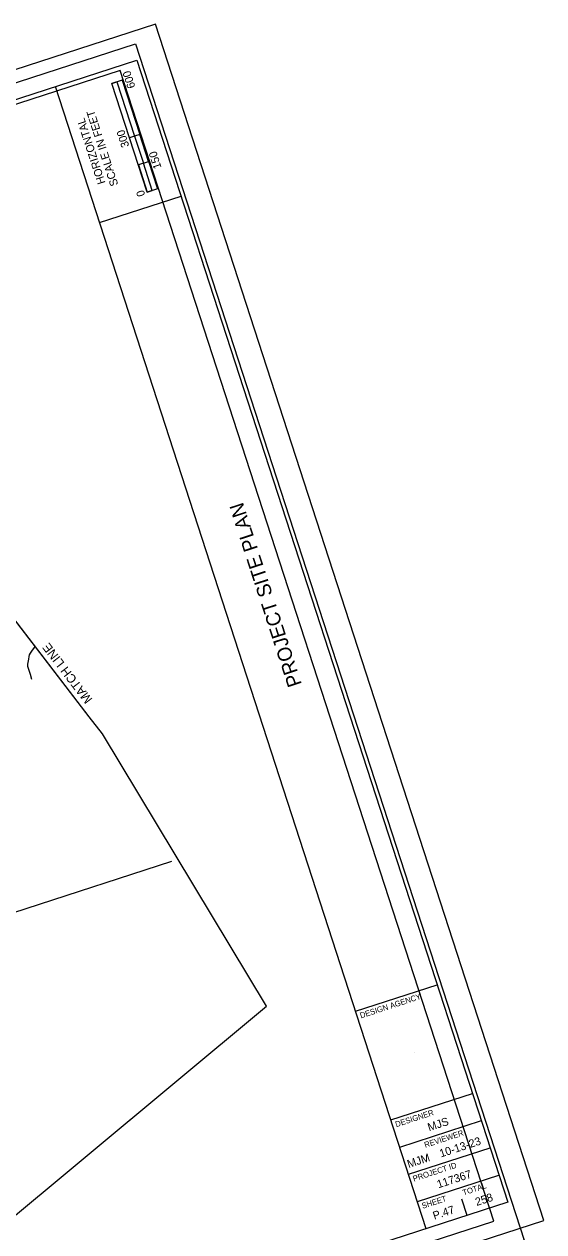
# Model space of a CAD drawing. Extents: x -468541894 to 3393103, y -306086142 to 1227927.
# Drawn here: x 1848366 to 1851093, y 537942 to 544279 of the extents above; entities that cross this region are included whole.
import ezdxf

# ---------------------------------------------------------------- set-up
doc = ezdxf.new("R2010")
doc.units = 0
for name, color, linetype in [('DT_X_Contour_Minor', 7, 'Continuous'), ('DT_X_Terrain_Ground_Line', 7, 'Continuous'), ('Level 14', 7, 'Continuous'), ('Level 63', 7, 'Continuous'), ('SC_Scratch1', 7, 'Continuous'), ('SH_Border', 7, 'Continuous'), ('SH_Cut_Line', 7, 'Continuous'), ('SH_Data', 7, 'Continuous')]:
    doc.layers.add(name, color=color, linetype=linetype)

msp = doc.modelspace()

# ---------------------------------------------------------------- linework, layer by layer
at = {"layer": 'DT_X_Contour_Minor'}
msp.add_lwpolyline([(1848407.5, 540841.3), (1848399.1, 540867.5), (1848386.1, 540908.3), (1848385.3, 540914.1), (1848386, 540921.4), (1848390.3, 540947.8), (1848392.7, 540960.7), (1848394.9, 540969.8), (1848399, 540978.1), (1848407.2, 540989.7), (1848420.5, 541008), (1848423.8, 541013.8)], dxfattribs=at)
at = {"layer": 'DT_X_Terrain_Ground_Line'}
msp.add_line((1848707.4, 540644.4), (1847509.3, 542205.2), dxfattribs=at)
at = {"layer": 'Level 14'}
msp.add_lwpolyline([(1845828.7, 538810.8), (1845878, 538827), (1845930.3, 538844), (1845983.1, 538861.1), (1846032.1, 538877.7), (1846083.4, 538894.3), (1849141.5, 539887)], dxfattribs=at)
at = {"layer": 'Level 63'}
for points in [[(1839250.2, 541026.2), (1848951, 544175.6), (1850988.8, 537898.9), (1841288, 534749.5)], [(1841356.9, 534923.2), (1850830.2, 537998.8), (1848870, 544036.6), (1839396.7, 540961)]]:
    msp.add_lwpolyline(points, close=True, dxfattribs=at)
at = {"layer": 'SC_Scratch1'}
msp.add_lwpolyline([(1841571, 538709.7), (1842189.3, 536805.3), (1843431.2, 536688.2), (1846191.5, 536987.1), (1848203, 537933.4), (1849637.7, 539126.1), (1848778.3, 540555.8), (1848707.4, 540644.4), (1847509.3, 542205.2), (1846552.9, 542298.5), (1845079.9, 541287.2), (1841825, 539212.4)], close=True, dxfattribs=at)
at = {"layer": 'SH_Border'}
for p, q in [((1850475.8, 537958.8), (1848530.4, 543951)), ((1848762, 543237.6), (1849190, 543376.6)), ((1850105.3, 539100.2), (1850533.3, 539239.2)), ((1850290.5, 538529.5), (1850718.5, 538668.5)), ((1850336.9, 538386.9), (1850764.9, 538525.8)), ((1850383.2, 538244.2), (1850811.2, 538383.1)), ((1850429.5, 538101.5), (1850857.5, 538240.5))]:
    msp.add_line(p, q, dxfattribs=at)
msp.add_lwpolyline([(1839827.6, 541125.5), (1848958.4, 544089.9), (1850903.8, 538097.8), (1841773, 535133.4)], close=True, dxfattribs=at)
at = {"layer": 'SH_Cut_Line'}
msp.add_lwpolyline([(1841391.3, 534851.8), (1851092.8, 538001.5), (1849054.8, 544278.9), (1839353.3, 541129.2)], close=True, dxfattribs=at)
at = {"layer": 'SH_Data'}
for p, q in [((1848880.1, 543985.6), (1848826.6, 543968.3)), ((1848826.6, 543968.3), (1848853.2, 543976.9)), ((1849011.8, 543397.6), (1848826.6, 543968.3)), ((1848919.2, 543682.9), (1848826.6, 543968.3)), ((1848853.2, 543976.9), (1848853.4, 543977)), ((1848853.4, 543977), (1848946.1, 543691.6)), ((1848880.1, 543985.6), (1849065.3, 543414.9)), ((1848946.1, 543691.6), (1848919.2, 543682.9)), ((1848972.5, 543700.2), (1848945.8, 543691.6)), ((1848945.8, 543691.6), (1848992.1, 543548.9)), ((1849018.8, 543557.5), (1848972.5, 543700.2)), ((1848992.1, 543548.9), (1848965.5, 543540.2)), ((1848992.1, 543548.9), (1849018.8, 543557.5)), ((1849038.5, 543406.2), (1848992.1, 543548.9)), ((1848965.5, 543540.2), (1849011.8, 543397.6)), ((1849065.3, 543414.9), (1849011.8, 543397.6)), ((1849011.8, 543397.6), (1849038.5, 543406.2)), ((1850411.9, 538884.3), (1850411.9, 538884.3)), ((1850689.8, 538028.3), (1850662, 538113.9)), ((1850566.6, 538043.5), (1850566.6, 538043.5))]:
    msp.add_line(p, q, dxfattribs=at)

# ---------------------------------------------------------------- texts
at = {"layer": 'SC_Scratch1'}
msp.add_text('MATCH LINE                  STA. 1840+00', height=46.8, rotation=127.51131, dxfattribs=at).set_placement((1848726.6, 540736.7))
at = {"layer": 'SH_Data'}
for s, height, rotation, p in [('600', 42, 107.9864, (1848950.6, 543949.2)), ('SCALE IN FEET', 42, 107.9864, (1848860.7, 543436.5)), ('HORIZONTAL', 42, 107.9864, (1848793.5, 543446.7)), ('300', 42, 107.9864, (1848918.8, 543639.2)), ('150', 42, 107.9864, (1849087.7, 543527)), ('0', 42, 107.9864, (1849002.2, 543382.2)), ('PROJECT SITE PLAN', 75, 107.9864, (1849824.4, 540815.3)), ('DESIGN AGENCY', 30, 17.9864, (1850133.4, 539062)), ('DESIGNER', 30, 17.9864, (1850318.7, 538491.4)), ('MJS', 42, 17.9864, (1850490.9, 538470)), ('REVIEWER', 30, 17.9864, (1850471.1, 538383.1)), ('10-13-23', 42, 17.9864, (1850552.9, 538332.4)), ('MJM', 42, 17.9864, (1850383.6, 538277.4)), ('PROJECT ID', 30, 17.9864, (1850411.3, 538206)), ('117367', 42, 17.9864, (1850539.6, 538170.4)), ('TOTAL', 30, 17.9864, (1850671.7, 538132.8)), ('SHEET', 30, 17.9864, (1850457.7, 538063.3)), ('258', 42, 17.9864, (1850740.6, 538077.9)), ('P.47', 42, 17.9864, (1850518.4, 538005.8))]:
    msp.add_text(s, height=height, rotation=rotation, dxfattribs=at).set_placement(p)

doc.saveas('drawing.dxf')
